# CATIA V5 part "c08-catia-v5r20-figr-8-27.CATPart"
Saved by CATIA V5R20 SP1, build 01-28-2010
Part number: Part2
Bounding box of the stored display mesh (mm): x -50 to 500, y -650 to 50, z 0 to 50
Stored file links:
  D:\v5_r20\psrt_files_downloaded\c08-catia-v5r20-prt\c08-catia-v5r20-figr-8-27.CATPart
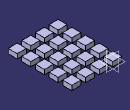
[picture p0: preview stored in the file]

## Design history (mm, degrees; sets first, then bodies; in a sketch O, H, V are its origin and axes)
Body1 (main body)
  Sketch1 on xy-plane, origin (0, 0, 0), H (1, 0, 0), V (0, 1, 0)
    line L1 (-50, 50) -> (50, 50)
    line L2 (50, 50) -> (50, -50)
    line L3 (50, -50) -> (-50, -50)
    line L4 (-50, -50) -> (-50, 50)
    axis line L5 (50, -50) -> (-50, 50)
    length L3 = 100
    length L2 = 100
    horizontal: L1 H, L3 H
    vertical: L2 V, L4 V
    midpoint: O L5
  Pad1: profile Sketch1, direction (0, 0, 1), length 50
  RectPattern1: of the body so far, direction 1 instances 4, spacing 150, along edge [face of Pad1 | face of Pad1], direction 2 instances 5, spacing 150, along edge [face of Pad1 | face of Pad1]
